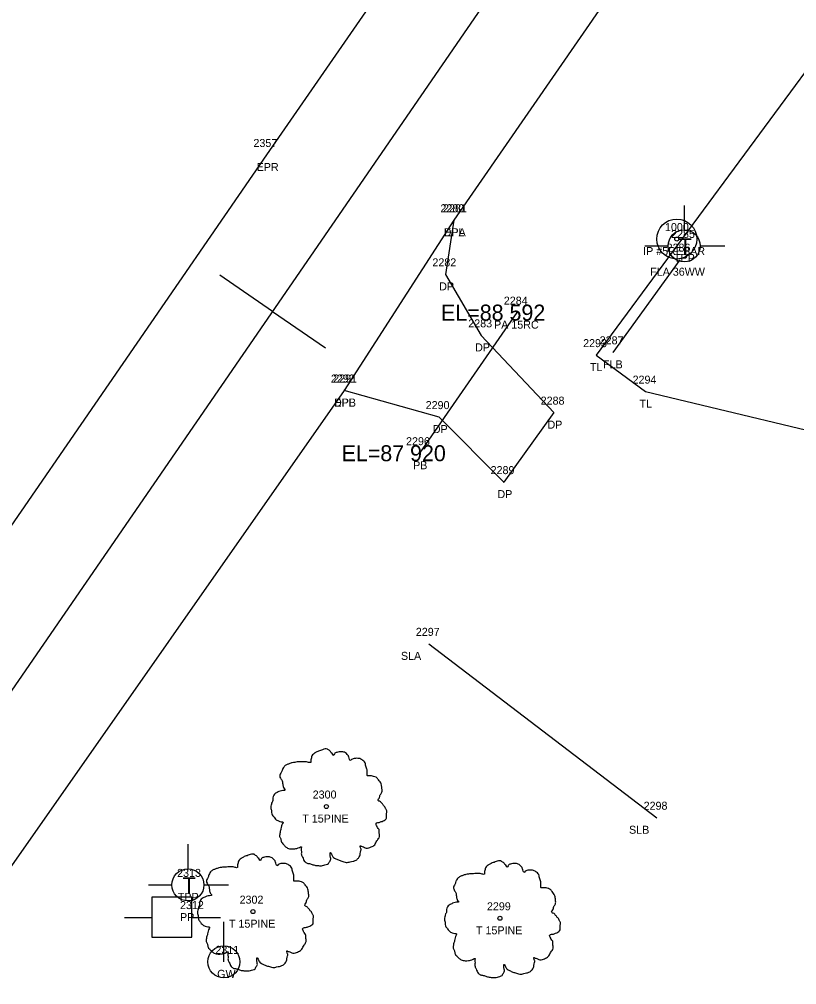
# Model space of a CAD drawing. Extents: x 2266664 to 2272542, y 716533 to 724777.
# Drawn here: x 2271573.7 to 2271670.7, y 723581.1 to 723701.7 of the extents above; entities that cross this region are included whole.
import ezdxf

# ---------------------------------------------------------------- set-up
doc = ezdxf.new("R2010")
doc.units = 0
for name, color, linetype in [('RD_EX_DR_Pipe', 7, 'Continuous'), ('RD_EX_DR_Pipe_txCode', 7, 'Continuous'), ('RD_EX_Driveway', 7, 'Continuous'), ('RD_EX_Driveway_txCode', 7, 'Continuous'), ('RD_EX_DV_Prop_txCode', 7, 'Continuous'), ('RD_EX_DV_PropPin', 7, 'Continuous'), ('RD_EX_Fence_Other', 7, 'Continuous'), ('RD_EX_Fence_Other_txCode', 7, 'Continuous'), ('RD_EX_Road', 7, 'Continuous'), ('RD_EX_Road_txCode', 7, 'Continuous'), ('RD_EX_UT', 7, 'Continuous'), ('RD_EX_UT_txCode', 7, 'Continuous'), ('RD_EX_VEG', 7, 'Continuous'), ('RD_EX_VEG_txCode', 7, 'Continuous'), ('RD_HC_Cl', 7, 'Continuous'), ('RD_HC_Data_Tic', 7, 'Continuous'), ('RD_SMD_Locator', 7, 'Continuous'), ('RD_TX_Pipe_ElevEX', 7, 'Continuous')]:
    doc.layers.add(name, color=color, linetype=linetype)

msp = doc.modelspace()

# ---------------------------------------------------------------- linework, layer by layer
at = {"layer": 'RD_EX_DR_Pipe'}
msp.add_line((2271635.8, 723665.08), (2271623.62, 723647.52), dxfattribs=at)
at = {"layer": 'RD_EX_Driveway'}
msp.add_lwpolyline([(2271627.92, 723676.62), (2271626.88, 723669.86), (2271631.36, 723662.24), (2271640.4, 723652.59), (2271634.15, 723643.91), (2271626.08, 723652.03), (2271614.21, 723655.35)], dxfattribs=at)
at = {"layer": 'RD_EX_DV_PropPin'}
for radius in [2.5, 0.25]:
    msp.add_circle((2271655.77, 723674.27), radius, dxfattribs=at)
at = {"layer": 'RD_EX_Fence_Other'}
msp.add_line((2271656.15, 723671.69), (2271647.77, 723660.12), dxfattribs=at)
at = {"layer": 'RD_EX_Road'}
for points in [[(2272350.52, 724770.05), (2272301.75, 724698.9), (2272265.2, 724646.02), (2272253.02, 724627.92), (2272200.51, 724550.87), (2272147.54, 724474.34), (2272126.28, 724443.66), (2272107.36, 724416.48), (2272092.2, 724393.69), (2272038.42, 724315.2), (2271991.52, 724247.47), (2271974.41, 724222.16), (2271928.73, 724155.87), (2271879.39, 724084.16), (2271852.9, 724045.63), (2271818.37, 723996.02), (2271765.12, 723918.77), (2271712.35, 723841.58), (2271659.05, 723763.61), (2271604.53, 723684.77), (2271550.65, 723606.61)], [(2272368.97, 724754.13), (2272346.57, 724721.92), (2272321.77, 724685.09), (2272273.25, 724614.42), (2272223.01, 724540.91), (2272206.83, 724517.64), (2272178.6, 724477.03), (2272166.48, 724459.37), (2272137.67, 724416.89), (2272108.53, 724374.93), (2272057.89, 724300.99), (2272036.24, 724269.85), (2272022.13, 724249.17), (2272003.16, 724221.27), (2271948.47, 724142.38), (2271900.7, 724072.99), (2271873.7, 724033.58), (2271837.94, 723981.87), (2271784.96, 723904.95), (2271732.12, 723828.06), (2271678.32, 723749.57), (2271627.92, 723676.62), (2271614.21, 723655.35), (2271570.62, 723593.07)]]:
    msp.add_lwpolyline(points, dxfattribs=at)
at = {"layer": 'RD_EX_UT'}
for p, q in [((2271656.69, 723678.48), (2271656.69, 723675.41)), ((2271651.76, 723673.43), (2271654.69, 723673.43)), ((2271658.69, 723673.43), (2271661.76, 723673.43)), ((2271594.72, 723598.67), (2271594.72, 723595.6)), ((2271589.79, 723593.61), (2271592.72, 723593.61)), ((2271596.72, 723593.61), (2271599.79, 723593.61)), ((2271595.22, 723592.09), (2271590.22, 723592.09)), ((2271590.22, 723592.09), (2271590.22, 723587.09)), ((2271595.22, 723587.09), (2271595.22, 723592.09)), ((2271586.79, 723589.53), (2271590.26, 723589.53)), ((2271595.15, 723589.53), (2271598.79, 723589.53)), ((2271599.21, 723583.99), (2271599.21, 723588.99)), ((2271590.22, 723587.09), (2271595.22, 723587.09))]:
    msp.add_line(p, q, dxfattribs=at)
for centre in [(2271656.69, 723673.41), (2271594.72, 723593.6), (2271599.21, 723583.99)]:
    msp.add_circle(centre, 2, dxfattribs=at)
at = {"layer": 'RD_EX_VEG'}
msp.add_line((2271624.81, 723623.71), (2271653.26, 723601.99), dxfattribs=at)
msp.add_lwpolyline([(2271723.21, 723697.3), (2271676.28, 723701.22), (2271645.7, 723659.77), (2271651.88, 723655.21), (2271681.05, 723648.22)], dxfattribs=at)
for centre, radius in [((2271612.01, 723603.39), 0.25), ((2271611.99, 723603.37), 0.0001), ((2271602.84, 723590.26), 0.25), ((2271602.83, 723590.24), 0.0001), ((2271633.69, 723589.43), 0.25), ((2271633.68, 723589.41), 0.0001)]:
    msp.add_circle(centre, radius, dxfattribs=at)
for points in [[(2271612.14, 723610.56), (2271611.84, 723610.58), (2271611.51, 723610.48), (2271611.26, 723610.38), (2271611.04, 723610.31), (2271610.81, 723610.21), (2271610.51, 723610.03), (2271610.29, 723609.83), (2271610.16, 723609.58), (2271610.11, 723609.36), (2271610.06, 723609.08), (2271610.06, 723608.91), (2271609.94, 723608.88), (2271609.79, 723608.91), (2271609.54, 723608.98), (2271609.29, 723608.98), (2271609.04, 723608.98), (2271608.69, 723608.96), (2271608.34, 723608.96), (2271608.06, 723608.91), (2271607.74, 723608.86), (2271607.37, 723608.73), (2271607.02, 723608.61), (2271606.72, 723608.36), (2271606.47, 723607.88), (2271606.34, 723607.54), (2271606.19, 723607.29), (2271606.34, 723606.84), (2271606.52, 723606.49), (2271606.54, 723606.29), (2271606.62, 723605.86), (2271606.72, 723605.64), (2271606.84, 723605.44), (2271606.77, 723605.41), (2271606.39, 723605.36), (2271606.09, 723605.26), (2271605.67, 723605.04), (2271605.44, 723604.81), (2271605.34, 723604.49), (2271605.32, 723604.14), (2271605.22, 723603.94), (2271605.14, 723603.66), (2271605.12, 723603.59), (2271605.07, 723603.26), (2271605.17, 723602.81), (2271605.19, 723602.46), (2271605.32, 723602.24), (2271605.47, 723602.06), (2271605.64, 723601.81), (2271606.04, 723601.59), (2271606.37, 723601.49), (2271606.57, 723601.46), (2271606.39, 723600.96), (2271606.34, 723600.61), (2271606.22, 723600.21), (2271606.22, 723600.14), (2271606.17, 723599.66), (2271606.32, 723599.34), (2271606.39, 723598.96), (2271606.57, 723598.74), (2271606.84, 723598.44), (2271607.17, 723598.21), (2271607.67, 723598.09), (2271608.06, 723598.11), (2271608.64, 723598.29), (2271608.89, 723598.36), (2271608.86, 723598.19), (2271608.89, 723597.81), (2271608.89, 723597.39), (2271609.04, 723597.06), (2271609.14, 723596.79), (2271609.29, 723596.54), (2271609.61, 723596.32), (2271610.01, 723596.24), (2271610.44, 723596.09), (2271610.89, 723596.02), (2271611.39, 723595.99), (2271611.99, 723596.14), (2271612.26, 723596.27), (2271612.36, 723596.44), (2271612.56, 723596.81), (2271612.51, 723597.04), (2271612.54, 723597.64), (2271612.64, 723597.46), (2271612.81, 723597.11), (2271613.31, 723596.81), (2271613.71, 723596.64), (2271614.19, 723596.49), (2271614.49, 723596.41), (2271614.96, 723596.49), (2271615.34, 723596.56), (2271615.71, 723596.69), (2271616.01, 723596.96), (2271616.19, 723597.24), (2271616.24, 723597.51), (2271616.31, 723597.89), (2271616.36, 723598.06)], [(2271616.36, 723598.06), (2271616.29, 723598.24), (2271616.24, 723598.49), (2271616.31, 723598.46), (2271616.49, 723598.41), (2271616.76, 723598.29), (2271616.99, 723598.21), (2271617.31, 723598.24), (2271617.59, 723598.34), (2271618.04, 723598.61), (2271618.31, 723599.09), (2271618.59, 723599.49), (2271618.66, 723599.81), (2271618.61, 723600.04), (2271618.59, 723600.54), (2271618.39, 723600.79), (2271618.34, 723600.91), (2271618.24, 723601.31), (2271618.31, 723601.36), (2271618.59, 723601.41), (2271618.96, 723601.54), (2271619.24, 723601.66), (2271619.46, 723601.84), (2271619.53, 723602.06), (2271619.51, 723602.46), (2271619.56, 723602.86), (2271619.48, 723603.01), (2271619.38, 723603.16), (2271619.31, 723603.36), (2271619.16, 723603.51), (2271619.06, 723603.66), (2271618.96, 723603.76), (2271618.84, 723603.91), (2271618.66, 723604.04), (2271618.51, 723604.09), (2271618.46, 723604.24), (2271618.61, 723604.44), (2271618.66, 723604.54), (2271618.69, 723604.76), (2271618.91, 723605.11), (2271618.96, 723605.51), (2271618.91, 723605.94), (2271618.86, 723606.21), (2271618.71, 723606.49), (2271618.51, 723606.74), (2271618.39, 723606.91), (2271618.21, 723607.04), (2271617.89, 723607.16), (2271617.64, 723607.21), (2271617.29, 723607.21), (2271617.09, 723607.26), (2271617.11, 723607.31), (2271617.11, 723607.46), (2271617.11, 723607.74), (2271617.04, 723608.18), (2271616.89, 723608.68), (2271616.89, 723608.71), (2271616.79, 723608.96), (2271616.56, 723609.16), (2271616.39, 723609.26), (2271616.19, 723609.38), (2271615.94, 723609.41), (2271615.64, 723609.41), (2271615.36, 723609.36), (2271615.16, 723609.26), (2271614.99, 723609.13), (2271614.91, 723609.28), (2271614.81, 723609.58), (2271614.76, 723609.73), (2271614.61, 723609.91), (2271614.39, 723610.11), (2271613.94, 723610.23), (2271613.31, 723610.16), (2271613.01, 723609.96), (2271612.86, 723609.78), (2271612.81, 723609.91), (2271612.61, 723610.11), (2271612.51, 723610.28), (2271612.34, 723610.41), (2271612.19, 723610.51), (2271612.09, 723610.56)], [(2271602.97, 723597.43), (2271602.67, 723597.45), (2271602.35, 723597.35), (2271602.1, 723597.25), (2271601.87, 723597.18), (2271601.65, 723597.08), (2271601.35, 723596.9), (2271601.12, 723596.7), (2271601, 723596.45), (2271600.95, 723596.23), (2271600.9, 723595.95), (2271600.9, 723595.78), (2271600.78, 723595.75), (2271600.63, 723595.78), (2271600.38, 723595.85), (2271600.13, 723595.85), (2271599.88, 723595.85), (2271599.53, 723595.83), (2271599.18, 723595.83), (2271598.9, 723595.78), (2271598.58, 723595.73), (2271598.2, 723595.6), (2271597.85, 723595.48), (2271597.55, 723595.23), (2271597.3, 723594.75), (2271597.18, 723594.4), (2271597.03, 723594.15), (2271597.18, 723593.7), (2271597.35, 723593.36), (2271597.38, 723593.16), (2271597.45, 723592.73), (2271597.55, 723592.51), (2271597.68, 723592.31), (2271597.6, 723592.28), (2271597.23, 723592.23), (2271596.93, 723592.13), (2271596.5, 723591.91), (2271596.28, 723591.68), (2271596.18, 723591.36), (2271596.15, 723591.01), (2271596.05, 723590.81), (2271595.98, 723590.53), (2271595.95, 723590.46), (2271595.9, 723590.13), (2271596, 723589.68), (2271596.03, 723589.33), (2271596.15, 723589.11), (2271596.3, 723588.93), (2271596.48, 723588.68), (2271596.88, 723588.46), (2271597.2, 723588.36), (2271597.4, 723588.33), (2271597.23, 723587.83), (2271597.18, 723587.48), (2271597.05, 723587.08), (2271597.05, 723587.01), (2271597, 723586.53), (2271597.15, 723586.21), (2271597.23, 723585.83), (2271597.4, 723585.61), (2271597.68, 723585.31), (2271598, 723585.08), (2271598.5, 723584.96), (2271598.9, 723584.98), (2271599.48, 723585.16), (2271599.73, 723585.23), (2271599.7, 723585.06), (2271599.73, 723584.68), (2271599.73, 723584.26), (2271599.88, 723583.93), (2271599.98, 723583.66), (2271600.13, 723583.41), (2271600.45, 723583.18), (2271600.85, 723583.11), (2271601.27, 723582.96), (2271601.72, 723582.88), (2271602.22, 723582.86), (2271602.82, 723583.01), (2271603.1, 723583.13), (2271603.2, 723583.31), (2271603.4, 723583.68), (2271603.35, 723583.91), (2271603.37, 723584.51), (2271603.47, 723584.33), (2271603.65, 723583.98), (2271604.15, 723583.68), (2271604.55, 723583.51), (2271605.02, 723583.36), (2271605.32, 723583.28), (2271605.8, 723583.36), (2271606.17, 723583.43), (2271606.55, 723583.56), (2271606.85, 723583.83), (2271607.02, 723584.11), (2271607.07, 723584.38), (2271607.15, 723584.76), (2271607.2, 723584.93)], [(2271607.2, 723584.93), (2271607.12, 723585.11), (2271607.07, 723585.36), (2271607.15, 723585.33), (2271607.32, 723585.28), (2271607.6, 723585.16), (2271607.82, 723585.08), (2271608.15, 723585.11), (2271608.42, 723585.21), (2271608.87, 723585.48), (2271609.15, 723585.96), (2271609.42, 723586.36), (2271609.5, 723586.68), (2271609.45, 723586.91), (2271609.42, 723587.41), (2271609.22, 723587.66), (2271609.17, 723587.78), (2271609.07, 723588.18), (2271609.15, 723588.23), (2271609.42, 723588.28), (2271609.8, 723588.41), (2271610.07, 723588.53), (2271610.3, 723588.71), (2271610.37, 723588.93), (2271610.35, 723589.33), (2271610.4, 723589.73), (2271610.32, 723589.88), (2271610.22, 723590.03), (2271610.15, 723590.23), (2271610, 723590.38), (2271609.9, 723590.53), (2271609.8, 723590.63), (2271609.67, 723590.78), (2271609.5, 723590.91), (2271609.35, 723590.96), (2271609.3, 723591.11), (2271609.45, 723591.31), (2271609.5, 723591.41), (2271609.52, 723591.63), (2271609.75, 723591.98), (2271609.8, 723592.38), (2271609.75, 723592.81), (2271609.7, 723593.08), (2271609.55, 723593.36), (2271609.35, 723593.6), (2271609.22, 723593.78), (2271609.05, 723593.9), (2271608.72, 723594.03), (2271608.47, 723594.08), (2271608.12, 723594.08), (2271607.92, 723594.13), (2271607.95, 723594.18), (2271607.95, 723594.33), (2271607.95, 723594.6), (2271607.87, 723595.05), (2271607.72, 723595.55), (2271607.72, 723595.58), (2271607.62, 723595.83), (2271607.4, 723596.03), (2271607.22, 723596.13), (2271607.02, 723596.25), (2271606.77, 723596.28), (2271606.47, 723596.28), (2271606.2, 723596.23), (2271606, 723596.13), (2271605.82, 723596), (2271605.75, 723596.15), (2271605.65, 723596.45), (2271605.6, 723596.6), (2271605.45, 723596.78), (2271605.22, 723596.98), (2271604.77, 723597.1), (2271604.15, 723597.03), (2271603.85, 723596.83), (2271603.7, 723596.65), (2271603.65, 723596.78), (2271603.45, 723596.98), (2271603.35, 723597.15), (2271603.17, 723597.28), (2271603.02, 723597.38), (2271602.92, 723597.43)], [(2271633.82, 723596.59), (2271633.52, 723596.62), (2271633.2, 723596.52), (2271632.95, 723596.42), (2271632.72, 723596.34), (2271632.5, 723596.24), (2271632.2, 723596.07), (2271631.97, 723595.87), (2271631.85, 723595.62), (2271631.8, 723595.4), (2271631.75, 723595.12), (2271631.75, 723594.95), (2271631.62, 723594.92), (2271631.47, 723594.95), (2271631.22, 723595.02), (2271630.97, 723595.02), (2271630.72, 723595.02), (2271630.37, 723595), (2271630.02, 723595), (2271629.75, 723594.95), (2271629.42, 723594.9), (2271629.05, 723594.77), (2271628.7, 723594.65), (2271628.4, 723594.4), (2271628.15, 723593.92), (2271628.03, 723593.57), (2271627.88, 723593.32), (2271628.03, 723592.87), (2271628.2, 723592.52), (2271628.23, 723592.32), (2271628.3, 723591.9), (2271628.4, 723591.67), (2271628.52, 723591.47), (2271628.45, 723591.45), (2271628.08, 723591.4), (2271627.78, 723591.3), (2271627.35, 723591.07), (2271627.13, 723590.85), (2271627.03, 723590.52), (2271627, 723590.17), (2271626.9, 723589.97), (2271626.83, 723589.7), (2271626.8, 723589.62), (2271626.75, 723589.3), (2271626.85, 723588.85), (2271626.88, 723588.5), (2271627, 723588.27), (2271627.15, 723588.1), (2271627.33, 723587.85), (2271627.73, 723587.62), (2271628.05, 723587.52), (2271628.25, 723587.5), (2271628.08, 723587), (2271628.03, 723586.65), (2271627.9, 723586.25), (2271627.9, 723586.17), (2271627.85, 723585.7), (2271628, 723585.37), (2271628.08, 723585), (2271628.25, 723584.78), (2271628.52, 723584.48), (2271628.85, 723584.25), (2271629.35, 723584.13), (2271629.75, 723584.15), (2271630.32, 723584.33), (2271630.57, 723584.4), (2271630.55, 723584.23), (2271630.57, 723583.85), (2271630.57, 723583.43), (2271630.72, 723583.1), (2271630.82, 723582.83), (2271630.97, 723582.58), (2271631.3, 723582.35), (2271631.7, 723582.28), (2271632.12, 723582.13), (2271632.57, 723582.05), (2271633.07, 723582.03), (2271633.67, 723582.18), (2271633.95, 723582.3), (2271634.05, 723582.48), (2271634.25, 723582.85), (2271634.2, 723583.08), (2271634.22, 723583.68), (2271634.32, 723583.5), (2271634.5, 723583.15), (2271635, 723582.85), (2271635.4, 723582.68), (2271635.87, 723582.53), (2271636.17, 723582.45), (2271636.65, 723582.53), (2271637.02, 723582.6), (2271637.4, 723582.73), (2271637.7, 723583), (2271637.87, 723583.28), (2271637.92, 723583.55), (2271638, 723583.93), (2271638.05, 723584.1)], [(2271638.05, 723584.1), (2271637.97, 723584.28), (2271637.92, 723584.53), (2271638, 723584.5), (2271638.17, 723584.45), (2271638.45, 723584.33), (2271638.67, 723584.25), (2271639, 723584.28), (2271639.27, 723584.38), (2271639.72, 723584.65), (2271639.99, 723585.12), (2271640.27, 723585.52), (2271640.34, 723585.85), (2271640.29, 723586.07), (2271640.27, 723586.57), (2271640.07, 723586.82), (2271640.02, 723586.95), (2271639.92, 723587.35), (2271639.99, 723587.4), (2271640.27, 723587.45), (2271640.64, 723587.57), (2271640.92, 723587.7), (2271641.14, 723587.87), (2271641.22, 723588.1), (2271641.19, 723588.5), (2271641.24, 723588.9), (2271641.17, 723589.05), (2271641.07, 723589.2), (2271640.99, 723589.4), (2271640.84, 723589.55), (2271640.74, 723589.7), (2271640.64, 723589.8), (2271640.52, 723589.95), (2271640.34, 723590.07), (2271640.19, 723590.12), (2271640.14, 723590.27), (2271640.29, 723590.47), (2271640.34, 723590.57), (2271640.37, 723590.8), (2271640.59, 723591.15), (2271640.64, 723591.55), (2271640.59, 723591.97), (2271640.54, 723592.25), (2271640.39, 723592.52), (2271640.19, 723592.77), (2271640.07, 723592.95), (2271639.89, 723593.07), (2271639.57, 723593.2), (2271639.32, 723593.25), (2271638.97, 723593.25), (2271638.77, 723593.3), (2271638.8, 723593.35), (2271638.8, 723593.5), (2271638.8, 723593.77), (2271638.72, 723594.22), (2271638.57, 723594.72), (2271638.57, 723594.75), (2271638.47, 723595), (2271638.25, 723595.2), (2271638.07, 723595.3), (2271637.87, 723595.42), (2271637.62, 723595.45), (2271637.32, 723595.45), (2271637.05, 723595.4), (2271636.85, 723595.3), (2271636.67, 723595.17), (2271636.6, 723595.32), (2271636.5, 723595.62), (2271636.45, 723595.77), (2271636.3, 723595.95), (2271636.07, 723596.15), (2271635.62, 723596.27), (2271635, 723596.2), (2271634.7, 723596), (2271634.55, 723595.82), (2271634.5, 723595.95), (2271634.3, 723596.15), (2271634.2, 723596.32), (2271634.02, 723596.44), (2271633.87, 723596.54), (2271633.77, 723596.59)]]:
    msp.add_spline(points, degree=3, dxfattribs=at)
at = {"layer": 'RD_HC_Cl'}
msp.add_line((2267342.91, 717471.2), (2272360.46, 724762.59), dxfattribs=at)
at = {"layer": 'RD_HC_Data_Tic'}
for q in [(2271598.71, 723669.74), (2271611.89, 723660.67)]:
    msp.add_line((2271605.3, 723665.21), q, dxfattribs=at)
at = {"layer": 'RD_SMD_Locator'}
for centre in [(2271604.53, 723684.77), (2271627.92, 723676.62), (2271627.92, 723676.62), (2271656.15, 723671.69), (2271626.88, 723669.86), (2271635.8, 723665.08), (2271631.36, 723662.24), (2271645.7, 723659.77), (2271647.77, 723660.12), (2271614.21, 723655.35), (2271614.21, 723655.35), (2271651.88, 723655.21), (2271640.4, 723652.59), (2271626.08, 723652.03), (2271623.62, 723647.52), (2271634.15, 723643.91), (2271624.81, 723623.71), (2271653.26, 723601.99)]:
    msp.add_circle(centre, 0.001, dxfattribs=at)

# ---------------------------------------------------------------- texts
at = {"layer": 'RD_EX_DR_Pipe_txCode'}
for s, p in [('2284', (2271634.17, 723666.08)), ('PA 15RC', (2271632.95, 723663.08)), ('2296', (2271621.96, 723648.52)), ('PB', (2271622.84, 723645.52))]:
    msp.add_text(s, height=1, dxfattribs=at).set_placement(p)
at = {"layer": 'RD_EX_Driveway_txCode'}
for s, p in [('2281', (2271626.58, 723677.62)), ('DPA', (2271626.66, 723674.62)), ('2282', (2271625.25, 723670.86)), ('DP', (2271626.1, 723667.86)), ('2283', (2271629.73, 723663.24)), ('DP', (2271630.58, 723660.24)), ('2291', (2271612.86, 723656.35)), ('DPB', (2271612.96, 723653.35)), ('2290', (2271624.41, 723653.03)), ('2288', (2271638.77, 723653.59)), ('DP', (2271639.62, 723650.59)), ('DP', (2271625.3, 723650.03)), ('2289', (2271632.52, 723644.91)), ('DP', (2271633.37, 723641.91))]:
    msp.add_text(s, height=1, dxfattribs=at).set_placement(p)
at = {"layer": 'RD_EX_DV_Prop_txCode'}
for s, p in [('1000', (2271654.3, 723675.27)), ('IP #5REBAR', (2271651.57, 723672.27))]:
    msp.add_text(s, height=1, dxfattribs=at).set_placement(p)
at = {"layer": 'RD_EX_Fence_Other_txCode'}
for s, p in [('2286', (2271654.5, 723672.69)), ('FLA 36WW', (2271652.45, 723669.69)), ('2287', (2271646.14, 723661.12)), ('FLB', (2271646.56, 723658.12))]:
    msp.add_text(s, height=1, dxfattribs=at).set_placement(p)
at = {"layer": 'RD_EX_Road_txCode'}
for s, p in [('2357', (2271602.9, 723685.77)), ('EPR', (2271603.3, 723682.77)), ('2280', (2271626.26, 723677.62)), ('EPL', (2271626.72, 723674.62)), ('2292', (2271612.58, 723656.35)), ('EPL', (2271613, 723653.35))]:
    msp.add_text(s, height=1, dxfattribs=at).set_placement(p)
at = {"layer": 'RD_EX_UT'}
for p in [(2271656.02, 723672.36), (2271594.05, 723592.55)]:
    msp.add_text('T', height=2, dxfattribs=at).set_placement(p)
at = {"layer": 'RD_EX_UT_txCode'}
for s, p in [('2285', (2271655.06, 723674.41)), ('TPP', (2271655.42, 723671.41)), ('2313', (2271593.37, 723594.6)), ('TPP', (2271593.45, 723591.6)), ('2312', (2271593.73, 723590.58)), ('PP', (2271593.73, 723589.08)), ('2311', (2271598.15, 723584.99)), ('GW', (2271598.37, 723581.99))]:
    msp.add_text(s, height=1, dxfattribs=at).set_placement(p)
at = {"layer": 'RD_EX_VEG_txCode'}
for s, p in [('2293', (2271644.07, 723660.77)), ('TL', (2271644.93, 723657.77)), ('2294', (2271650.25, 723656.21)), ('TL', (2271651.11, 723653.21)), ('2297', (2271623.18, 723624.71)), ('SLA', (2271621.32, 723621.71)), ('2300', (2271610.3, 723604.39)), ('2298', (2271651.63, 723602.99)), ('T 15PINE', (2271609, 723601.39)), ('SLB', (2271649.81, 723599.99)), ('2302', (2271601.17, 723591.26)), ('2299', (2271632.06, 723590.43)), ('T 15PINE', (2271599.84, 723588.26)), ('T 15PINE', (2271630.69, 723587.43))]:
    msp.add_text(s, height=1, dxfattribs=at).set_placement(p)
at = {"layer": 'RD_TX_Pipe_ElevEX'}
for s, p in [('EL=88 592  ', (2271626.33, 723664.08)), ('EL=87 920  ', (2271613.91, 723646.52))]:
    msp.add_text(s, height=2, dxfattribs=at).set_placement(p)

doc.saveas('drawing.dxf')
